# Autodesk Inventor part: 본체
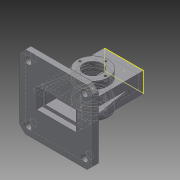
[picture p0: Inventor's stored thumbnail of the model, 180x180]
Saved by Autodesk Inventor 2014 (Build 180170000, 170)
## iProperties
Created: 2016-02
Part Number: 본체
Material: Generic
Document SubType Name: Modeling
Designer: user
Density: 1 g/cm^3
Appearance: Default
Author: user
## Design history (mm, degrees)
sketch "Sketch1"
  geometry: L1 (-34.681, 55)-(35.319, 55); L2 (35.319, 55)-(35.319, -55); L3 (35.319, -55)-(-34.681, -55); L4 (-34.681, -55)-(-34.681, 55); 1 further point
  constraints: 8 end point, 2 parallel, 1 horizontal, 1 perpendicular
  dimensions: "d0" = 70 distance of L1.start L1.end; "d1" = 110 distance of L1.end L2.end
extrude "Extrusion1" new body sketch "Sketch1" stored distance "d4" = 35; taper "d5" = 0 deg
sketch "Sketch2"
  geometry: C1 r 27.5 at (0, 0); 1 further point
  constraints: 1 centre point, 1 coincident
  dimensions: "d6" = 55 diameter of C1
extrude "Extrusion2" join sketch "Sketch2" distance "d7" = 13; taper "d8" = 0 deg
shell "Shell1" dims "d9" = 5
sketch "Sketch3"
  geometry: 4 further points
hole "Hole1" sketch "Sketch3" at (0, 22.5), (-22.5, 0), (0, -22.5), (22.5, 0) diameter "d11" = 4; stored, may be unused: countersink angle "d15" = 90 deg, drill point angle "d17" = 118 deg; dims "d12" = 6, "d13" = 9.4, "d14" = 4.775, "d16" = 8
sketch "Sketch4"
  geometry: C1 r 27.5 at (0, 0) reference; C2 r 16 at (0, 0)
  constraints: 1 centre point, 1 coincident
  dimensions: "d18" = 32 diameter of C2
extrude "Extrusion3" cut sketch "Sketch4" stored distance "d19" = 13; taper "d20" = 0 deg
sketch "Sketch5"
  geometry: C1 r 22.5 at (30.319, -50) reference; C2 r 27.5 at (30.319, -50)
  constraints: 1 centre point, 1 coincident
  dimensions: "d21" = 55 diameter of C2
extrude "Extrusion4" join sketch "Sketch5" distance "d22" = 7; taper "d23" = -45 deg
mirror "Mirror1"
sketch "Sketch6"
  geometry: L1 (70, 0)-(70, -35) reference; L2 (0, 0)-(70, 0) reference; L3 (0, 0)-(0, -35) reference; L4 (70, -35)-(0, -35) reference; L5 (-30.319, 47.5)-(99.681, 47.5); L6 (99.681, 47.5)-(99.681, -82.5); L7 (99.681, -82.5)-(-30.319, -82.5); L8 (-30.319, -82.5)-(-30.319, 47.5); 1 further point
  constraints: 8 end point, 2 parallel, 1 horizontal, 1 perpendicular
  dimensions: "d24" = 130 distance of L5.start L5.end; "d25" = 130 distance of L5.end L6.end; "d26" = 65 horizontal distance of L5.end point (34.681, -17.5); "d27" = 65 distance from line of L8 point (34.681, -17.5)
extrude "Extrusion5" join sketch "Sketch6" distance "d28" = 10; taper "d29" = 0 deg
sketch "Sketch7"
  geometry: L1 (-15.319, 67.5)-(84.681, 67.5); L2 (84.681, 67.5)-(84.681, -32.5); L3 (84.681, -32.5)-(-15.319, -32.5); L4 (-15.319, -32.5)-(-15.319, 67.5); 2 further points
  constraints: 8 end point, 2 parallel, 1 horizontal, 1 perpendicular
  dimensions: "d30" = 100 distance of L1.start L1.end; "d31" = 100 distance of L1.end L2.end; "d32" = 15 horizontal distance of L1.end point (99.681, 82.5); "d33" = 15 horizontal distance of point (99.681, 82.5) L1.end
hole "Hole2" sketch "Sketch7" at (84.681, 67.5), (84.681, -32.5), (-15.319, -32.5), (-15.319, 67.5) diameter "d34" = 12; stored, may be unused: countersink angle "d38" = 90 deg, drill point angle "d40" = 0 deg; dims "d35" = 6, "d36" = 9.4, "d37" = 4.775, "d39" = 8
chamfer "Chamfer1" distance "d41" = 10; stored, may be unused: second distance "d42" = 2, angle "d43" = 45 deg
sketch "Sketch8"
  geometry: 1 further point
sketch "Sketch9"
  geometry: L1 (49.987, -54.91)-(32.643, 43.454); L2 (32.643, 43.454)-(32.643, -54.91); L3 (49.987, -54.91)-(32.643, -54.91); 1 further point
  constraints: 6 end point, 1 perpendicular
extrude "Extrusion6" join sketch "Sketch9" stored distance "d48" = 5; taper "d49" = 0 deg
mirror "Mirror2"
sketch "Sketch10"
  geometry: L1 (0, 35)-(0, 0) reference; L2 (70, 0)-(0, 0) reference; L3 (70, 0)-(70, 35) reference; L4 (0, 35)-(70, 35) reference; 1 further point
body "Solid1"
